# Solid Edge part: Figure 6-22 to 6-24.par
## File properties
Author: CADCIM
Template: Normal.par
Last saved by: Ashutosh-CADCIM
Revision: 5
Application: Solid Edge
Accuracy: 0.99
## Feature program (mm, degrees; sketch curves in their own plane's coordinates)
sketch for "unnamed Protrusion 1" plane through (0, 0, 0) normal (0, -1, 0) x-axis (1, 0, 0)
  line (-47.9688, 40.4319) -> (-47.9688, 0)
  line (-47.9688, 0) -> (40.7735, 0)
  line (40.7735, 0) -> (11.4256, 32.2563)
  arc centre (-7.0661, 15.4319) radius 25 from (11.4256, 32.2563) to (-7.0661, 40.4319) ccw
  line (-7.0661, 40.4319) -> (-47.9688, 40.4319)
extrude "unnamed Protrusion 1" add finite 57.15 symmetric
sketch for "ExtrudedProtrusion_3" plane through (18.5879, 0, 24.3842) normal (0.739666, 0, 0.672975) x-axis (0, 1, 0)
  circle centre (0, -8.0136) radius 16.4586
extrude "ExtrudedProtrusion_3" add finite 41.275 along +normal
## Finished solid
Body 1: solid body, 9 faces, 17 edges, 10 vertices.
  Faces by surface: plane 7, cylinder 2
  Edges by curve: line 13, circle 4
Bounding box of the edges (mm): 113.556 x 57.150 x 58.408, from (-47.9688, -28.575, 0) to (65.5868, 28.575, 58.4077).
Cylindrical faces by radius (mm): R16.4586 x1, R25 x1
Planar faces by outward normal: +y 1, +z 1, -x 1, -y 1, -z 1, oblique 2
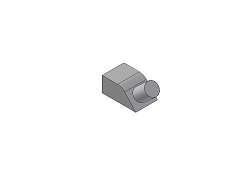
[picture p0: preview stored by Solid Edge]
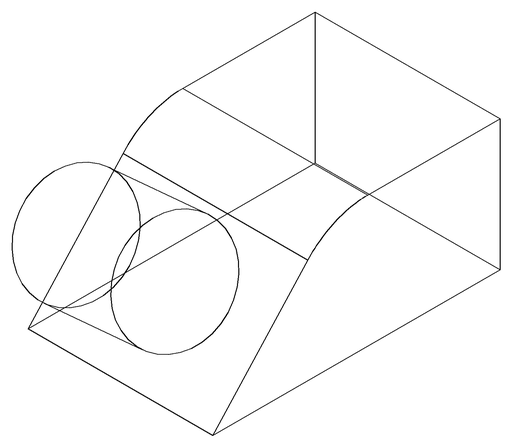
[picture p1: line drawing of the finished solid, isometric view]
